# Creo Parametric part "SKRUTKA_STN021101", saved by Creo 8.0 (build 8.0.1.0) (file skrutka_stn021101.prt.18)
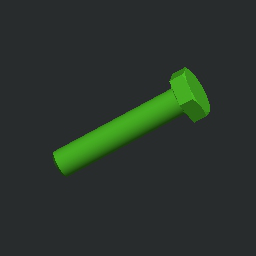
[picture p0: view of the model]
Units: Custom; MM, KILOGRAM, SECS
Materials in the file: OCEL_N

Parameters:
  KATEGORIE = "4"
  NAZOV = "SKRUTKA_STN021101"
  NORMA = "STN 02 1101"
  N2 = "21"
  N3 = "1"
  PTC_MATERIAL_NAME = "OCEL_N"
  PLACEMENT = "A"

Other parameters: HMOTNOST, HUSTOTA, HMOTNOST_1, D42, D2, D7, D25, D30, D1, D41, THREADS_PER_INCH

Created from: STN_021101_SKRUTKA_6HR.PRT

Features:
  1. chamfer
  2. datum plane "DTM1"
  3. protrusion
  4. datum plane "DTM6"
  5. cut
  6. datum plane "DTM7"
  7. cut
  8. datum plane "DTM8"
  9. datum plane "DTM9"

Layers: BEZUGSEBENEN, NORMTEILE

Family table entries: SKRUTKA_M3X16, SKRUTKA_STN021101, value(d_val), 2/0, 2/(, value(i_val), SKRUTKA_M3X20, SKRUTKA_STN021101, 2/4, 2/(, SKRUTKA_M3X25, SKRUTKA_STN021101, 2/9, 2/(, SKRUTKA_M4X25, SKRUTKA_STN021101, 2/9, 2/,, SKRUTKA_M4X30, SKRUTKA_STN021101, 2/>, 2/,, SKRUTKA_M4X35, SKRUTKA_STN021101, 2/,, SKRUTKA_M4X40, SKRUTKA_STN021101, 2/D, 2/,, SKRUTKA_M5X25, SKRUTKA_STN021101, 2/9, 2/ , 2/0, SKRUTKA_M5X30, SKRUTKA_STN021101, 2/>, 2/ , 2/0, SKRUTKA_M5X35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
